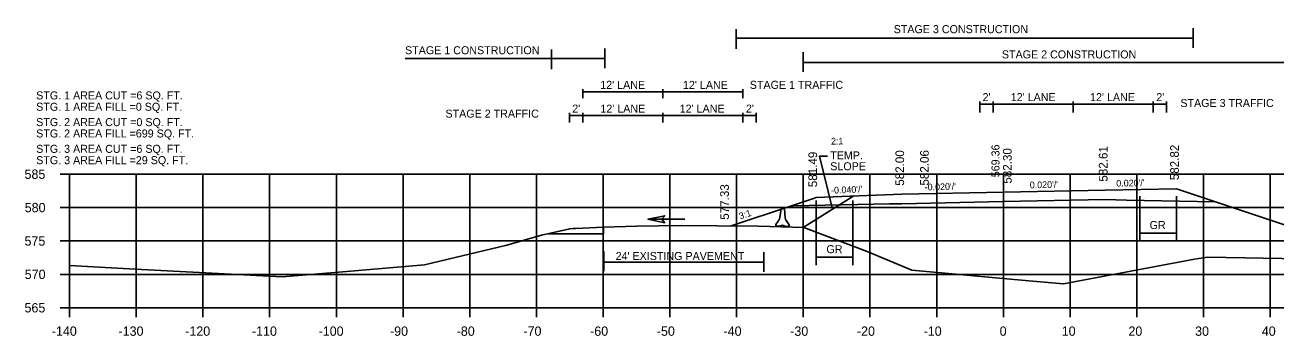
# Model space of a CAD drawing. Extents: x 642114 to 642416, y 286928 to 293347.
# Drawn here: x 642113.6 to 642301.1, y 290342.3 to 290388.9 of the extents above; entities that cross this region are included whole.
import ezdxf

# ---------------------------------------------------------------- set-up
doc = ezdxf.new("R2010")
doc.units = 0
for name, color, linetype in [('Level 43', 7, 'Continuous'), ('Level 58', 7, 'Continuous'), ('R_Axis', 7, 'Continuous'), ('R_Axis Annot', 7, 'Continuous'), ('R_Draft', 7, 'Continuous'), ('R_Exist Surface', 7, 'Continuous'), ('R_Exist Surface Annot', 7, 'Continuous'), ('R_Fin Surface', 7, 'Continuous'), ('R_Grid', 7, 'Continuous'), ('R_MOT Barrier', 7, 'Continuous'), ('R_Xsect Elev', 7, 'Continuous'), ('R_Xsect Slope', 7, 'Continuous')]:
    doc.layers.add(name, color=color, linetype=linetype)

# ---------------------------------------------------------------- blocks, each defined once
blk = doc.blocks.new('BARRIER WALL X-SECTION')
at = {"layer": 'R_MOT Barrier'}
for p, q in [((0.8, 2.59), (0.63, 1.29)), ((0.8, 2.59), (0.87, 2.65)), ((0.87, 2.65), (1.24, 2.64)), ((1.24, 2.64), (1.31, 2.58)), ((1.31, 2.58), (1.42, 1.27)), ((0.48, 0.9), (0, 0.25)), ((0, 0.25), (0, 0)), ((0.5, -0.01), (0, 0)), ((0.5, -0.01), (1, 0.15)), ((1, 0.15), (1.5, -0.03)), ((1.56, 0.88), (2, 0.21)), ((2, 0.21), (2, -0.04)), ((1.5, -0.03), (2, -0.04))]:
    blk.add_line(p, q, dxfattribs=at)
for centre, start, end in [((-0.2, 1.39), 323.8622, 352.8452), ((2.25, 1.34), 184.8632, 213.8462)]:
    blk.add_arc(centre, 0.833, start, end, dxfattribs=at)
blk = doc.blocks.new('FA')
at = {"layer": 'Level 43'}
blk.add_lwpolyline([(7.94, 0), (0, 0)], dxfattribs=at)
at = {"layer": 'Level 58'}
blk.add_lwpolyline([(4.34, 0.75), (7.94, 0), (4.34, -0.75), (4.94, 0)], close=True, dxfattribs=at)

msp = doc.modelspace()

# ---------------------------------------------------------------- linework, layer by layer
at = {"layer": 'R_Axis'}
for p, q in [((642118.84, 290366.52), (642120.24, 290366.52)), ((642120.24, 290346.52), (642120.24, 290366.52)), ((642118.84, 290361.52), (642120.24, 290361.52)), ((642118.84, 290356.52), (642120.24, 290356.52)), ((642118.84, 290351.52), (642120.24, 290351.52)), ((642118.84, 290346.52), (642120.24, 290346.52)), ((642120.24, 290346.52), (642400.24, 290346.52)), ((642120.24, 290345.12), (642120.24, 290346.52)), ((642130.24, 290345.12), (642130.24, 290346.52)), ((642140.24, 290345.12), (642140.24, 290346.52)), ((642150.24, 290345.12), (642150.24, 290346.52)), ((642160.24, 290345.12), (642160.24, 290346.52)), ((642170.24, 290345.12), (642170.24, 290346.52)), ((642180.24, 290345.12), (642180.24, 290346.52)), ((642190.24, 290345.12), (642190.24, 290346.52)), ((642200.24, 290345.12), (642200.24, 290346.52)), ((642210.24, 290345.12), (642210.24, 290346.52)), ((642220.24, 290345.12), (642220.24, 290346.52)), ((642230.24, 290345.12), (642230.24, 290346.52)), ((642240.24, 290345.12), (642240.24, 290346.52)), ((642250.24, 290345.12), (642250.24, 290346.52)), ((642260.24, 290345.12), (642260.24, 290346.52)), ((642270.24, 290345.12), (642270.24, 290346.52)), ((642280.24, 290345.12), (642280.24, 290346.52)), ((642290.24, 290345.12), (642290.24, 290346.52)), ((642300.24, 290345.12), (642300.24, 290346.52))]:
    msp.add_line(p, q, dxfattribs=at)
at = {"layer": 'R_Exist Surface'}
msp.add_lwpolyline([(642228.47, 290361.77), (642228.74, 290361.78), (642243.18, 290362.06), (642243.35, 290362.07), (642244.99, 290362.1), (642260.24, 290362.41), (642275.49, 290362.71), (642278.7, 290362.65), (642291.93, 290362.38), (642292.06, 290362.38)], dxfattribs=at)
at = {"layer": 'R_Exist Surface Annot'}
msp.add_lwpolyline([(642120.24, 290352.84), (642130.08, 290352.32), (642152.1, 290351.15), (642161.21, 290351.91), (642173.44, 290352.93), (642185.78, 290355.88), (642190.99, 290357.39), (642195.24, 290358.34), (642195.76, 290358.39), (642196.13, 290358.41), (642200.28, 290358.61), (642205.31, 290358.73), (642211.76, 290358.85), (642217.26, 290358.8), (642223.49, 290358.73), (642226.97, 290358.62), (642230.3, 290358.53), (642239.84, 290354.93), (642246.49, 290352.13), (642264.06, 290350.53), (642269.27, 290350.1), (642288.91, 290353.78), (642290.82, 290354.09), (642293.65, 290354.04), (642324.15, 290353.51)], dxfattribs=at)
at = {"layer": 'R_Fin Surface'}
msp.add_lwpolyline([(642219.45, 290358.77), (642228.47, 290361.77), (642231.77, 290362.87), (642232.18, 290363.01), (642244.99, 290363.52), (642260.24, 290363.82), (642275.49, 290364.13), (642286.18, 290364.34), (642318.41, 290353.61)], dxfattribs=at)
at = {"layer": 'R_Grid'}
for p, q in [((642120.24, 290366.52), (642400.24, 290366.52)), ((642120.24, 290346.52), (642120.24, 290366.52)), ((642130.24, 290346.52), (642130.24, 290366.52)), ((642140.24, 290346.52), (642140.24, 290366.52)), ((642150.24, 290346.52), (642150.24, 290366.52)), ((642160.24, 290346.52), (642160.24, 290366.52)), ((642170.24, 290346.52), (642170.24, 290366.52)), ((642180.24, 290346.52), (642180.24, 290366.52)), ((642190.24, 290346.52), (642190.24, 290366.52)), ((642200.24, 290346.52), (642200.24, 290366.52)), ((642210.24, 290346.52), (642210.24, 290366.52)), ((642220.24, 290346.52), (642220.24, 290366.52)), ((642230.24, 290346.52), (642230.24, 290366.52)), ((642240.24, 290346.52), (642240.24, 290366.52)), ((642250.24, 290346.52), (642250.24, 290366.52)), ((642260.24, 290346.52), (642260.24, 290366.52)), ((642270.24, 290346.52), (642270.24, 290366.52)), ((642280.24, 290346.52), (642280.24, 290366.52)), ((642290.24, 290346.52), (642290.24, 290366.52)), ((642300.24, 290346.52), (642300.24, 290366.52)), ((642120.24, 290361.52), (642400.24, 290361.52)), ((642120.24, 290356.52), (642400.24, 290356.52)), ((642120.24, 290351.52), (642400.24, 290351.52)), ((642120.24, 290346.52), (642400.24, 290346.52))]:
    msp.add_line(p, q, dxfattribs=at)
at = {"layer": 'R_Xsect Elev'}
for p, q in [((642220.17, 290385.31), (642220.17, 290388.24)), ((642288.67, 290385.45), (642288.67, 290388.37)), ((642220.17, 290386.88), (642288.67, 290386.88)), ((642192.51, 290382.25), (642192.51, 290385.18)), ((642200.47, 290382.39), (642200.47, 290385.32)), ((642230.24, 290381.86), (642230.24, 290384.79)), ((642170.54, 290383.86), (642200.47, 290383.86)), ((642230.24, 290383.24), (642316.22, 290383.24)), ((642197.18, 290377.93), (642197.18, 290379.25)), ((642197.18, 290378.84), (642221.18, 290378.84)), ((642209.18, 290377.93), (642209.18, 290379.25)), ((642221.18, 290377.93), (642221.18, 290379.25)), ((642256.7, 290375.76), (642256.7, 290377.42)), ((642256.7, 290377), (642284.7, 290377)), ((642258.7, 290375.76), (642258.7, 290377.42)), ((642270.7, 290375.76), (642270.7, 290377.42)), ((642282.7, 290375.76), (642282.7, 290377.42)), ((642284.7, 290375.76), (642284.7, 290377.42)), ((642195.18, 290374.27), (642195.18, 290375.7)), ((642195.18, 290375.29), (642223.18, 290375.29)), ((642197.18, 290374.27), (642197.18, 290375.7)), ((642209.18, 290374.27), (642209.18, 290375.7)), ((642221.18, 290374.27), (642221.18, 290375.7)), ((642223.18, 290374.27), (642223.18, 290375.7)), ((642232.18, 290352.92), (642232.18, 290362.59)), ((642237.68, 290352.92), (642237.68, 290362.59)), ((642280.68, 290356.54), (642280.68, 290363.23)), ((642286.18, 290356.54), (642286.18, 290363.23)), ((642286.15, 290357.7), (642280.68, 290357.7)), ((642200.35, 290351.99), (642200.35, 290354.92)), ((642224.35, 290351.9), (642224.35, 290354.83)), ((642200.35, 290353.34), (642224.35, 290353.34)), ((642232.2, 290354.08), (642237.68, 290354.08))]:
    msp.add_line(p, q, dxfattribs=at)
for points in [[(642233.87, 290369.22), (642232.65, 290369.22)], [(642232.65, 290369.22), (642234.61, 290361.27)], [(642232.65, 290369.22), (642234.61, 290361.27)], [(642237.8, 290363.26), (642230.24, 290358.53)], [(642192, 290357.61), (642200.28, 290357.61), (642200.28, 290358.61)]]:
    msp.add_lwpolyline(points, dxfattribs=at)

# ---------------------------------------------------------------- block references
at = {"layer": 'R_Xsect Elev', "xscale": 0.7, "yscale": 0.7, "rotation": 179.99999999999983}
msp.add_blockref('FA', (642212.5, 290359.78), dxfattribs=at)
at = {"layer": 'R_Xsect Elev'}
msp.add_blockref('BARRIER WALL X-SECTION', (642226.1, 290358.73), dxfattribs=at)

# ---------------------------------------------------------------- texts
at = {"layer": 'R_Axis Annot'}
for s, p in [('585', (642113.49, 290365.82)), ('580', (642113.52, 290360.82)), ('575', (642113.49, 290355.82)), ('570', (642113.52, 290350.82)), ('565', (642113.49, 290345.82)), ('-140', (642117.58, 290342.32)), ('-130', (642127.58, 290342.32)), ('-120', (642137.58, 290342.32)), ('-110', (642147.58, 290342.32)), ('-100', (642157.58, 290342.32)), ('-90', (642168.28, 290342.32)), ('-80', (642178.28, 290342.32)), ('-70', (642188.28, 290342.32)), ('-60', (642198.28, 290342.32)), ('-50', (642208.28, 290342.32)), ('-40', (642218.28, 290342.32)), ('-30', (642228.28, 290342.32)), ('-20', (642238.28, 290342.32)), ('-10', (642248.28, 290342.32)), ('0', (642259.68, 290342.32)), ('10', (642268.98, 290342.32)), ('20', (642278.98, 290342.32)), ('30', (642288.98, 290342.32)), ('40', (642298.98, 290342.32))]:
    msp.add_text(s, height=1.4, dxfattribs=at).set_placement(p)
at = {"layer": 'R_Draft'}
for s, p in [('STG. 1 AREA CUT =6 SQ. FT.', (642115.24, 290377.72)), ('STG. 1 AREA FILL =0 SQ. FT.', (642115.24, 290376.02)), ('STG. 2 AREA CUT =0 SQ. FT.', (642115.24, 290373.72)), ('STG. 2 AREA FILL =699 SQ. FT.', (642115.24, 290372.02)), ('STG. 3 AREA CUT =6 SQ. FT.', (642115.24, 290369.72)), ('STG. 3 AREA FILL =29 SQ. FT.', (642115.24, 290368.02))]:
    msp.add_text(s, height=1.2, dxfattribs=at).set_placement(p)
at = {"layer": 'R_Xsect Elev'}
for s, p in [('STAGE 3 CONSTRUCTION', (642243.79, 290387.64)), ('STAGE 1 CONSTRUCTION', (642170.54, 290384.48)), ('STAGE 2 CONSTRUCTION', (642260.01, 290383.86)), ("12' LANE", (642199.8, 290379.3)), ("12' LANE", (642212.2, 290379.29)), ('STAGE 1 TRAFFIC', (642222.22, 290379.3)), ("2'", (642257.12, 290377.46)), ("12' LANE", (642261.34, 290377.46)), ("12' LANE", (642273.23, 290377.46)), ("2'", (642283.16, 290377.46)), ("2'", (642195.6, 290375.74)), ("12' LANE", (642199.82, 290375.74)), ("12' LANE", (642211.71, 290375.74)), ("2'", (642221.64, 290375.74)), ('STAGE 3 TRAFFIC', (642286.77, 290376.58)), ('STAGE 2 TRAFFIC', (642176.6, 290374.99)), ('TEMP.', (642234.28, 290368.74)), ('SLOPE', (642234.28, 290367.11)), ('GR', (642282.16, 290358.31)), ("24' EXISTING PAVEMENT", (642202.1, 290353.67)), ('GR', (642233.71, 290354.69))]:
    msp.add_text(s, height=1.2, dxfattribs=at).set_placement(p)
for s, height, p in [(' 581.49', 1.3, (642232.31, 290364.09)), (' 582.00', 1.3, (642245.35, 290364.31)), (' 582.06', 1.3, (642249.05, 290364.33)), ('569.36', 1.2, (642259.65, 290366.06)), (' 582.30', 1.3, (642261.48, 290364.62)), (' 582.61', 1.3, (642275.85, 290364.92)), (' 582.82', 1.3, (642286.54, 290365.14)), (' 577.33', 1.3, (642219.09, 290359.22))]:
    msp.add_text(s, height=height, rotation=90, dxfattribs=at).set_placement(p)
at = {"layer": 'R_Xsect Slope'}
for s, rotation, p in [('2:1', 0.32, (642234.4, 290370.96)), ("0.020'/'", 1.1458, (642264.2, 290364.4)), ("0.020'/'", 1.147, (642277.17, 290364.66)), ("-0.040'/'", 2.2906, (642234.42, 290363.6)), ("-0.020'/'", 1.1458, (642248.45, 290364.09)), ('3:1', 18.3966, (642220.79, 290359.72))]:
    msp.add_text(s, height=1, rotation=rotation, dxfattribs=at).set_placement(p)

doc.saveas('drawing.dxf')
